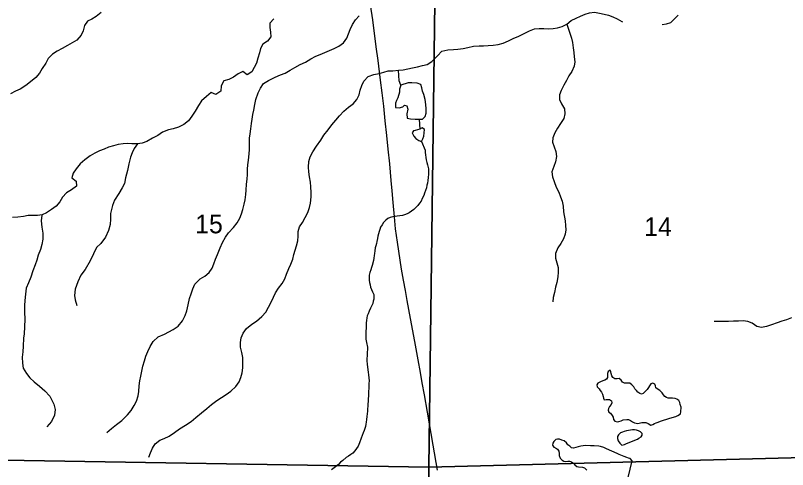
# Model space of a CAD drawing. Extents: x 0 to 34, y 0 to 22.
# Drawn here: x 6.524 to 8.26, y 15.118 to 16.139 of the extents above; entities that cross this region are included whole.
import ezdxf

# ---------------------------------------------------------------- set-up
doc = ezdxf.new("R2010")
doc.units = 0
for name, color, linetype in [('GM_X_Corporation', 7, 'Continuous'), ('GM_X_Minor_Lake', 7, 'Continuous'), ('GM_X_Minor_River', 7, 'Continuous'), ('GM_X_Section_Text', 7, 'Continuous'), ('GM_X_State_Route', 7, 'Continuous')]:
    doc.layers.add(name, color=color, linetype=linetype)

msp = doc.modelspace()

# ---------------------------------------------------------------- linework, layer by layer
at = {"layer": 'GM_X_Corporation'}
for points in [[(6.4674, 16.2404), (7.4675, 16.2282), (7.4535, 15.1233), (6.4527, 15.1394)], [(7.4675, 16.2282), (8.4859, 16.2068), (8.4718, 15.1496), (7.4535, 15.1233)], [(6.4527, 15.1394), (7.4535, 15.1233), (7.4459, 14.1288), (6.4438, 14.1407)], [(8.4718, 15.1496), (8.4517, 14.1122), (7.4459, 14.1288), (7.4535, 15.1233)]]:
    msp.add_lwpolyline(points, close=True, dxfattribs=at)
at = {"layer": 'GM_X_Minor_Lake'}
for points in [[(7.9953, 15.2332), (8.0084, 15.2372), (8.0134, 15.2394), (8.0188, 15.2434), (8.0201, 15.2475), (8.0204, 15.2585), (8.0186, 15.2643), (8.0176, 15.2689), (8.0155, 15.2731), (8.0106, 15.2763), (8.0069, 15.2775), (8.0012, 15.2785), (7.997, 15.2782), (7.9917, 15.2787), (7.9876, 15.2796), (7.9838, 15.282), (7.9809, 15.2859), (7.9776, 15.2901), (7.9725, 15.296), (7.9687, 15.298), (7.9639, 15.3015), (7.9629, 15.3061), (7.9615, 15.31), (7.957, 15.3124), (7.9524, 15.3106), (7.9493, 15.3065), (7.9469, 15.3028), (7.9441, 15.2983), (7.939, 15.2924), (7.9351, 15.2891), (7.9313, 15.2873), (7.9275, 15.2889), (7.9234, 15.292), (7.9201, 15.2959), (7.9164, 15.2998), (7.9139, 15.3037), (7.9098, 15.3084), (7.905, 15.3119), (7.9012, 15.3124), (7.8971, 15.3122), (7.8929, 15.3123), (7.8888, 15.3147), (7.8855, 15.3189), (7.8814, 15.3225), (7.8769, 15.3222), (7.8715, 15.322), (7.8674, 15.3248), (7.8649, 15.3286), (7.8631, 15.3336), (7.8629, 15.3374), (7.8607, 15.3417), (7.8564, 15.3384), (7.8552, 15.3339), (7.8549, 15.3251), (7.8525, 15.3214), (7.8487, 15.3188), (7.8445, 15.3171), (7.8391, 15.3149), (7.8337, 15.3124), (7.8313, 15.3083), (7.8319, 15.3037), (7.836, 15.2998), (7.8385, 15.296), (7.8418, 15.2917), (7.844, 15.2874), (7.8454, 15.2821), (7.846, 15.2783), (7.8474, 15.2744), (7.852, 15.2751), (7.8558, 15.2753), (7.8596, 15.2752), (7.8641, 15.2724), (7.8651, 15.2682), (7.8631, 15.2641), (7.8595, 15.2596), (7.8571, 15.2551), (7.8563, 15.2514), (7.858, 15.2468), (7.8617, 15.2444), (7.8658, 15.2397), (7.8676, 15.2359), (7.8689, 15.2305), (7.8719, 15.2266), (7.8768, 15.225), (7.8806, 15.226), (7.8859, 15.2277), (7.8905, 15.2295), (7.8982, 15.2308), (7.9023, 15.2303), (7.9064, 15.2283), (7.9109, 15.2251), (7.9154, 15.2231), (7.9192, 15.2219), (7.9229, 15.2218), (7.9321, 15.2238), (7.9363, 15.224), (7.9412, 15.2235), (7.9461, 15.2215), (7.9525, 15.218)], [(7.9525, 15.218), (7.9566, 15.2193), (7.9605, 15.2215), (7.9647, 15.2229), (7.9686, 15.2243), (7.9739, 15.2264), (7.9953, 15.2332)], [(7.9222, 15.1863), (7.9258, 15.1882), (7.9304, 15.1911), (7.9332, 15.1953), (7.9333, 15.199), (7.9296, 15.2029), (7.9251, 15.2046), (7.9202, 15.2063), (7.9157, 15.2071), (7.9115, 15.2069), (7.9066, 15.2066), (7.9024, 15.206), (7.8978, 15.205), (7.8928, 15.2032), (7.8886, 15.2018), (7.884, 15.2001), (7.8797, 15.196), (7.8773, 15.1923), (7.8772, 15.1877), (7.8793, 15.1827), (7.883, 15.1773), (7.8871, 15.1725)], [(7.8765, 15.1537), (7.853, 15.1648), (7.847, 15.1677), (7.8395, 15.1698), (7.8354, 15.1706), (7.8251, 15.1709), (7.8214, 15.1714), (7.8168, 15.1715), (7.8066, 15.1718), (7.8005, 15.1712), (7.7952, 15.1706), (7.789, 15.1693), (7.7837, 15.1675), (7.7787, 15.1662), (7.7738, 15.1667), (7.7701, 15.1702), (7.7656, 15.1737), (7.7627, 15.178), (7.7575, 15.1823), (7.7527, 15.184), (7.7474, 15.186), (7.7429, 15.1862), (7.739, 15.1851), (7.7347, 15.1811), (7.732, 15.177), (7.7315, 15.1728), (7.7344, 15.1682), (7.7381, 15.1665), (7.7426, 15.1638), (7.7459, 15.1591), (7.7461, 15.1542), (7.7467, 15.1492), (7.7489, 15.1438), (7.7529, 15.1388), (7.7566, 15.1368), (7.7612, 15.1363), (7.7657, 15.1365), (7.7699, 15.1364), (7.774, 15.1351), (7.7785, 15.1323), (7.7814, 15.1285), (7.7859, 15.1249), (7.79, 15.1237), (7.7991, 15.1234), (7.8036, 15.1214), (7.8088, 15.1163)], [(7.8871, 15.1725), (7.8931, 15.1743), (7.8977, 15.1761), (7.9222, 15.1863)], [(7.9102, 15.1373), (7.9059, 15.1424), (7.9021, 15.1437), (7.8984, 15.1453), (7.8928, 15.1474), (7.8886, 15.149), (7.8815, 15.1519), (7.8765, 15.1537)], [(7.8923, 15.0626), (7.9102, 15.1373)]]:
    msp.add_lwpolyline(points, dxfattribs=at)
at = {"layer": 'GM_X_Minor_River'}
for points in [[(6.7172, 16.146), (6.706, 16.1372), (6.6959, 16.131), (6.6859, 16.1264), (6.6792, 16.1167), (6.6766, 16.1046), (6.6721, 16.0948), (6.6619, 16.0841), (6.6519, 16.0775), (6.6415, 16.0714), (6.6295, 16.0653), (6.618, 16.0591), (6.6076, 16.0526), (6.5982, 16.0422), (6.5926, 16.0321), (6.5842, 16.0198), (6.5783, 16.0097), (6.5704, 15.9997), (6.5583, 15.9897), (6.5475, 15.9821), (6.5351, 15.9737), (6.5244, 15.9687), (6.5132, 15.9633)], [(7.7737, 16.1277), (7.7846, 16.1332), (7.7945, 16.1376), (7.8045, 16.1424), (7.8144, 16.1452), (7.8258, 16.1469), (7.8368, 16.1448), (7.8474, 16.1423), (7.8572, 16.1402), (7.8674, 16.1359), (7.8771, 16.1315), (7.8869, 16.1257), (7.8888, 16.1253)], [(7.1053, 16.1317), (7.0963, 16.122), (7.0957, 16.1122), (7.0976, 16.1015), (7.0981, 16.0912), (7.0906, 16.0815), (7.0806, 16.075), (7.075, 16.0653), (7.0728, 16.0554), (7.0694, 16.043), (7.0661, 16.0321), (7.0612, 16.0223), (7.0553, 16.0126), (7.0448, 16.0057), (7.0352, 16.0136), (7.0248, 16.0078), (7.0147, 16.0008), (7.0036, 15.9954), (6.9928, 15.9919), (6.9868, 15.9811), (6.9861, 15.9693), (6.9749, 15.9613), (6.9644, 15.9661), (6.9535, 15.957), (6.9426, 15.947), (6.9355, 15.9369), (6.9279, 15.9242), (6.9208, 15.9127), (6.9129, 15.9022), (6.9024, 15.8938), (6.8909, 15.8877), (6.879, 15.8846), (6.8683, 15.8822), (6.8549, 15.8769), (6.844, 15.8692), (6.8325, 15.8631), (6.8198, 15.8558), (6.809, 15.852), (6.7984, 15.8507), (6.7862, 15.8503), (6.7764, 15.851), (6.7661, 15.8509), (6.7551, 15.8489), (6.7444, 15.8462), (6.7336, 15.8431), (6.7237, 15.8388), (6.7129, 15.8349), (6.7025, 15.8295), (6.6925, 15.8233), (6.6805, 15.8145), (6.67, 15.8053), (6.6609, 15.7942), (6.6538, 15.7845), (6.6509, 15.7743), (6.6609, 15.7665), (6.6617, 15.755), (6.6501, 15.747), (6.6393, 15.7405), (6.6303, 15.7308), (6.6239, 15.7204), (6.6157, 15.7107), (6.6056, 15.7027), (6.594, 15.695), (6.584, 15.6907), (6.5737, 15.6891), (6.5532, 15.6897), (6.5426, 15.6873), (6.53, 15.6854), (6.5178, 15.685)], [(6.7295, 15.201), (6.7403, 15.2102), (6.7512, 15.219), (6.7636, 15.2282), (6.7765, 15.2407), (6.7844, 15.2508), (6.7915, 15.2616), (6.7967, 15.2717), (6.8001, 15.2838), (6.8015, 15.2936), (6.8026, 15.3061), (6.8041, 15.3175), (6.8059, 15.3277), (6.8085, 15.3394), (6.8103, 15.3504), (6.8141, 15.3624), (6.8174, 15.3726), (6.8219, 15.3835), (6.8268, 15.3943), (6.8335, 15.4056), (6.8448, 15.4163), (6.8591, 15.4227), (6.8691, 15.4274), (6.8791, 15.4332), (6.8903, 15.4404), (6.8998, 15.4527), (6.9054, 15.4643), (6.9095, 15.4749), (6.9125, 15.4884), (6.9156, 15.5024), (6.9193, 15.513), (6.9227, 15.5246), (6.9275, 15.5348), (6.9392, 15.5466), (6.9496, 15.5528), (6.9597, 15.5608), (6.9661, 15.5705), (6.9705, 15.5807), (6.9742, 15.5908), (6.9784, 15.6017), (6.9845, 15.6168), (6.9897, 15.6288), (6.9965, 15.6404), (7.0029, 15.6504), (7.0142, 15.6623), (7.0229, 15.6727), (7.0288, 15.6831), (7.0325, 15.6929), (7.0355, 15.7027), (7.0381, 15.7148), (7.0403, 15.7246), (7.0421, 15.7364), (7.0432, 15.7462), (7.0439, 15.7595), (7.045, 15.7712), (7.0457, 15.7815), (7.046, 15.7936), (7.0467, 15.8035), (7.0481, 15.8141), (7.0496, 15.8277), (7.0503, 15.838), (7.0503, 15.8505), (7.0503, 15.8634), (7.0517, 15.8733), (7.0532, 15.8846), (7.055, 15.896), (7.0564, 15.9062), (7.0582, 15.9164), (7.0604, 15.9266), (7.0623, 15.9391), (7.0649, 15.9504), (7.0699, 15.9651), (7.0751, 15.976), (7.0815, 15.986), (7.0934, 15.9933), (7.1084, 16.0005), (7.1203, 16.0058), (7.1303, 16.0097), (7.1415, 16.0166), (7.1523, 16.0224), (7.1643, 16.0289), (7.1762, 16.0343), (7.1881, 16.0415), (7.1993, 16.0477), (7.2093, 16.0516), (7.2197, 16.0562), (7.2304, 16.0605), (7.2404, 16.0652), (7.2508, 16.0706), (7.2613, 16.0779), (7.2691, 16.0879), (7.2732, 16.098), (7.2765, 16.1078), (7.2818, 16.1187), (7.2889, 16.1291), (7.2968, 16.1388)], [(7.5188, 16.0634), (7.531, 16.0653), (7.5413, 16.0669), (7.5539, 16.07), (7.5665, 16.0708), (7.5764, 16.0713), (7.587, 16.0717), (7.5977, 16.0726), (7.6091, 16.0738), (7.6205, 16.0773), (7.6325, 16.0826), (7.6428, 16.0873), (7.6555, 16.0926), (7.669, 16.0995), (7.6801, 16.1048), (7.6909, 16.1091), (7.7015, 16.1096), (7.7121, 16.1096), (7.7224, 16.1093), (7.7326, 16.1098), (7.7425, 16.1111), (7.7533, 16.1142), (7.7637, 16.12), (7.7737, 16.1277)], [(7.9778, 16.1187), (7.9874, 16.1208), (7.9973, 16.1233), (8.0139, 16.14)], [(7.7637, 16.12), (7.7745, 16.0885), (7.7761, 16.0782), (7.7777, 16.0668), (7.7793, 16.0561), (7.7805, 16.0462), (7.7814, 16.0351), (7.7799, 16.0249), (7.7751, 16.0136), (7.7683, 16.0032), (7.7627, 15.9927), (7.7571, 15.9826), (7.7507, 15.9706), (7.747, 15.9608), (7.7471, 15.9502), (7.7517, 15.9402), (7.7583, 15.9294), (7.7594, 15.9179), (7.7569, 15.9074), (7.7493, 15.8962), (7.743, 15.8861), (7.737, 15.8752), (7.7321, 15.8644), (7.7315, 15.8545), (7.735, 15.8438), (7.7392, 15.833), (7.7404, 15.8223), (7.7382, 15.8102), (7.7341, 15.7993), (7.7303, 15.7877), (7.7311, 15.7762), (7.7354, 15.7655), (7.7396, 15.7532), (7.7453, 15.7416), (7.7496, 15.7316), (7.7531, 15.7217), (7.7551, 15.7106), (7.7562, 15.6976), (7.7602, 15.677), (7.7607, 15.6667), (7.7615, 15.6568), (7.7597, 15.647), (7.7564, 15.6372), (7.75, 15.626), (7.7433, 15.6163), (7.738, 15.6039), (7.7381, 15.5936), (7.7412, 15.5825), (7.7439, 15.5722), (7.7444, 15.5619), (7.7434, 15.5513), (7.7411, 15.5388), (7.7385, 15.5279), (7.7359, 15.5162), (7.7333, 15.5052), (7.7319, 15.495)], [(6.8243, 15.1455), (6.828, 15.1553), (6.8324, 15.1662), (6.838, 15.1759), (6.8485, 15.1836), (6.8585, 15.1879), (6.87, 15.1933), (6.882, 15.2009), (6.8932, 15.2093), (6.9064, 15.2177), (6.9191, 15.2257), (6.93, 15.2349), (6.9424, 15.2456), (6.9545, 15.2551), (6.9646, 15.2639), (6.977, 15.2735), (6.9878, 15.28), (6.9979, 15.2869), (7.0087, 15.2942), (7.02, 15.3046), (7.0271, 15.3154), (7.0312, 15.3251), (7.0338, 15.3353), (7.0352, 15.3467), (7.0352, 15.3581), (7.0351, 15.3699), (7.0332, 15.3813), (7.0305, 15.3932), (7.03, 15.4038), (7.0318, 15.414), (7.0359, 15.4249), (7.0438, 15.4354), (7.0559, 15.4449), (7.0663, 15.4518), (7.078, 15.4618), (7.087, 15.4721), (7.0934, 15.4834), (7.0986, 15.4931), (7.1043, 15.5059), (7.1091, 15.5156), (7.1158, 15.5257), (7.1241, 15.5365), (7.1301, 15.5469), (7.1338, 15.5571), (7.1387, 15.5699), (7.1435, 15.5796), (7.1477, 15.5913), (7.1502, 15.6018), (7.1561, 15.6214), (7.1587, 15.632), (7.1601, 15.6426), (7.16, 15.6532), (7.163, 15.6638), (7.1693, 15.6735), (7.1814, 15.696), (7.1855, 15.7072), (7.1877, 15.7171), (7.1888, 15.7311), (7.1887, 15.7413), (7.1883, 15.7535), (7.1875, 15.7646), (7.1855, 15.776), (7.1836, 15.7878), (7.1827, 15.7981), (7.1835, 15.8106), (7.1868, 15.8212), (7.1928, 15.8324), (7.2012, 15.8451), (7.211, 15.8585), (7.2174, 15.8697), (7.2273, 15.8824), (7.2355, 15.8932), (7.2442, 15.9036), (7.2528, 15.9132), (7.2626, 15.9239), (7.2731, 15.9331), (7.2835, 15.9408), (7.2918, 15.9505), (7.2966, 15.9606), (7.2988, 15.9716), (7.3026, 15.9821), (7.307, 15.9918), (7.3172, 16.0022), (7.3302, 16.0068), (7.342, 16.0091), (7.3523, 16.0115), (7.3623, 16.0146), (7.3725, 16.0151), (7.3855, 16.0159), (7.3957, 16.0171), (7.406, 16.0191), (7.4164, 16.0218), (7.4278, 16.0238), (7.4389, 16.0265), (7.4496, 16.0289), (7.46, 16.0354), (7.4733, 16.0483), (7.4827, 16.0587), (7.4964, 16.0621), (7.509, 16.0629), (7.5188, 16.0634)], [(7.3906, 15.9823), (7.3867, 15.9923), (7.3855, 16.0159)], [(7.4467, 15.9388), (7.4455, 15.9506), (7.442, 15.9613), (7.4396, 15.969), (7.4379, 15.9762), (7.4355, 15.9839), (7.4272, 15.9868), (7.4155, 15.9879), (7.4068, 15.9878), (7.3906, 15.9823)], [(7.3906, 15.9823), (7.3878, 15.9736), (7.3876, 15.9671), (7.3841, 15.9543), (7.3809, 15.9479), (7.3788, 15.9423), (7.3789, 15.9324), (7.3865, 15.9314), (7.3949, 15.9338), (7.3984, 15.9372), (7.4037, 15.9362), (7.4061, 15.9286), (7.4043, 15.918), (7.4044, 15.9081), (7.4119, 15.9064), (7.4225, 15.9057), (7.432, 15.9058), (7.4396, 15.9063), (7.4451, 15.9122), (7.4472, 15.9197), (7.4471, 15.9296), (7.4467, 15.9388)], [(7.432, 15.9058), (7.4336, 15.8837)], [(7.4386, 15.8862), (7.4336, 15.8837), (7.4283, 15.8823), (7.4225, 15.8806), (7.4187, 15.88), (7.4159, 15.8755), (7.4199, 15.8678), (7.4243, 15.8623), (7.4313, 15.8579), (7.437, 15.8559)], [(7.437, 15.8559), (7.4402, 15.8615), (7.4423, 15.8675), (7.4432, 15.8751), (7.4435, 15.883), (7.4386, 15.8862)], [(6.7984, 15.8507), (6.7914, 15.8402), (6.787, 15.8305), (6.7832, 15.8203), (6.779, 15.8053), (6.7759, 15.7909), (6.772, 15.7739), (6.7693, 15.7611), (6.7645, 15.7514), (6.7569, 15.7391), (6.747, 15.7238), (6.7424, 15.7122), (6.7381, 15.6937), (6.7381, 15.6812), (6.737, 15.6694), (6.7332, 15.6555), (6.727, 15.6409), (6.716, 15.6264), (6.7062, 15.6175), (6.6997, 15.6029), (6.692, 15.5872), (6.6812, 15.5678), (6.6713, 15.5548), (6.6644, 15.5402), (6.6583, 15.524), (6.6571, 15.5093), (6.6583, 15.4994), (6.6621, 15.4867)], [(7.437, 15.8559), (7.4452, 15.836), (7.4455, 15.8314), (7.4461, 15.8257), (7.4467, 15.8196), (7.4477, 15.8146), (7.449, 15.8089), (7.4508, 15.8031), (7.4528, 15.794), (7.453, 15.7894), (7.4528, 15.7822), (7.4522, 15.775), (7.4513, 15.7678), (7.4504, 15.7621), (7.4491, 15.7572), (7.4482, 15.7515), (7.444, 15.7395), (7.442, 15.7346), (7.4387, 15.7275), (7.4359, 15.7218), (7.4328, 15.7174), (7.4288, 15.7122), (7.4245, 15.7077), (7.4195, 15.7029), (7.4144, 15.6989), (7.409, 15.6952), (7.4044, 15.6931), (7.399, 15.691), (7.3944, 15.6896), (7.3883, 15.6886), (7.3826, 15.688), (7.3777, 15.6874), (7.3727, 15.686), (7.3666, 15.6847), (7.3612, 15.6829), (7.3565, 15.6785), (7.3518, 15.6733), (7.3487, 15.6684), (7.3451, 15.6632), (7.3431, 15.658), (7.3418, 15.6534), (7.3405, 15.6482), (7.3392, 15.6425), (7.3383, 15.6376), (7.3366, 15.6308), (7.3357, 15.6263), (7.334, 15.621), (7.3328, 15.6165), (7.3318, 15.6096), (7.3313, 15.604), (7.3304, 15.599), (7.3302, 15.593), (7.3293, 15.5884), (7.326, 15.5771), (7.3243, 15.5722), (7.323, 15.5673), (7.321, 15.5613), (7.3193, 15.5549), (7.3191, 15.5488), (7.3197, 15.5439), (7.3203, 15.5385), (7.3213, 15.5332), (7.3223, 15.5282), (7.3244, 15.5232), (7.3269, 15.5178), (7.3298, 15.5113), (7.33, 15.506), (7.3295, 15.501), (7.3286, 15.4965), (7.3273, 15.4916), (7.3245, 15.4856), (7.3221, 15.4807), (7.3192, 15.474), (7.3168, 15.4683), (7.3152, 15.4638), (7.3139, 15.4593), (7.313, 15.4532), (7.3124, 15.4479), (7.3116, 15.4172), (7.3118, 15.4115), (7.3131, 15.4038), (7.3154, 15.3931), (7.3157, 15.3882), (7.3151, 15.3821), (7.3146, 15.3776), (7.3145, 15.373), (7.314, 15.3681), (7.3142, 15.3631), (7.3147, 15.354), (7.3153, 15.3491), (7.3163, 15.3422), (7.3169, 15.3369), (7.3178, 15.3307), (7.3188, 15.3243), (7.319, 15.3174), (7.3188, 15.3113), (7.3186, 15.3056), (7.3182, 15.2893), (7.3176, 15.284), (7.3174, 15.2772), (7.3169, 15.2707)], [(6.584, 15.6907), (6.5836, 15.6903), (6.582, 15.6775), (6.5839, 15.663), (6.5857, 15.6493), (6.5861, 15.6359), (6.5835, 15.6243), (6.5805, 15.613), (6.5755, 15.6002), (6.5722, 15.5885), (6.5688, 15.578), (6.5635, 15.5645), (6.5585, 15.5506), (6.5536, 15.5378), (6.5487, 15.5258), (6.5458, 15.5054), (6.5445, 15.4887), (6.5444, 15.4716), (6.5451, 15.456), (6.5445, 15.4386), (6.5437, 15.4234), (6.5423, 15.4136), (6.5417, 15.3957), (6.541, 15.3829), (6.5395, 15.3704), (6.5398, 15.3574), (6.5417, 15.3456), (6.5494, 15.3336), (6.5563, 15.3239), (6.5663, 15.3153), (6.5785, 15.3058), (6.5903, 15.2948), (6.6017, 15.2827), (6.6107, 15.2653), (6.6133, 15.2527), (6.6118, 15.2402), (6.605, 15.226), (6.5947, 15.2142)], [(8.2689, 15.459), (8.2574, 15.4548), (8.2471, 15.452), (8.2367, 15.4478), (8.224, 15.4432), (8.2122, 15.4393), (8.2011, 15.4377), (8.1909, 15.4399), (8.1805, 15.4471), (8.1704, 15.4511), (8.1598, 15.4522), (8.1495, 15.4517), (8.1385, 15.4513), (8.1271, 15.4508), (8.1169, 15.4508), (8.1048, 15.4511), (8.0949, 15.4506)], [(7.3169, 15.2707), (7.3167, 15.2654), (7.3162, 15.2605), (7.3157, 15.2544), (7.3155, 15.2491), (7.315, 15.2434), (7.314, 15.237), (7.3131, 15.2302), (7.3125, 15.2241), (7.312, 15.2196), (7.3111, 15.215), (7.3099, 15.2105), (7.3082, 15.206), (7.3062, 15.2007), (7.3016, 15.1883), (7.2976, 15.1778), (7.2943, 15.1703), (7.2911, 15.1651), (7.2868, 15.1602), (7.2825, 15.155), (7.2778, 15.1514), (7.2728, 15.1481), (7.2678, 15.1448), (7.26, 15.1386), (7.255, 15.1342), (7.2503, 15.1294), (7.2437, 15.1242), (7.2344, 15.1176)]]:
    msp.add_lwpolyline(points, dxfattribs=at)
at = {"layer": 'GM_X_State_Route'}
msp.add_lwpolyline([(7.3218, 16.1634), (7.3265, 16.1296), (7.3345, 16.0686), (7.3387, 16.0378), (7.3442, 15.9935), (7.348, 15.9652), (7.3512, 15.9356), (7.3548, 15.9022), (7.358, 15.8695), (7.3615, 15.8386), (7.3647, 15.8053), (7.368, 15.7682), (7.3701, 15.7447), (7.3726, 15.7183), (7.3754, 15.6861), (7.3779, 15.6595), (7.3799, 15.6442), (7.382, 15.6294), (7.3913, 15.5686), (7.3959, 15.5436), (7.4, 15.521), (7.4042, 15.4978), (7.4079, 15.4776), (7.4225, 15.3976), (7.4286, 15.3646), (7.4338, 15.3359), (7.4381, 15.3127), (7.4427, 15.2857), (7.4495, 15.2466), (7.4628, 15.1727), (7.4723, 15.1163)], dxfattribs=at)

# ---------------------------------------------------------------- texts
at = {"layer": 'GM_X_Section_Text'}
for s, p in [('15', (6.9282, 15.6493)), ('14', (7.9374, 15.6432))]:
    msp.add_text(s, height=0.04186, rotation=0, dxfattribs=at).set_placement(p)

doc.saveas('drawing.dxf')
